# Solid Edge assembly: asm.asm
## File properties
Author: Deepak Maini
Template: Normal.asm
Last saved by: CADCIM
Revision: 7
Application: Solid Edge
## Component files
multi-1-plate.par
multi-2-plate.par
multi-3.par
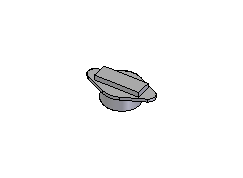
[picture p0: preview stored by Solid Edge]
